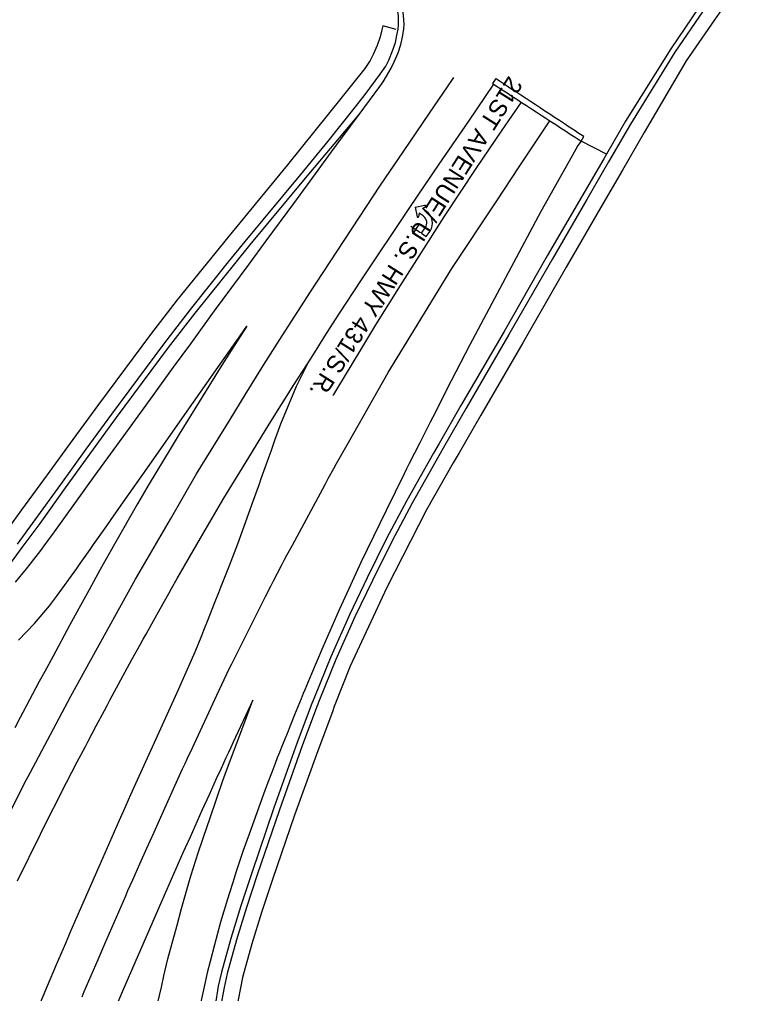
# Model space of a CAD drawing. Extents: x 1729281 to 1732101, y 650763 to 653805.
# Drawn here: x 1730490.5 to 1730745, y 652950.8 to 653286.3 of the extents above; entities that cross this region are included whole.
import ezdxf

# ---------------------------------------------------------------- set-up
doc = ezdxf.new("R2010")
doc.units = 0
for name, color, linetype in [('SURVEY - ROADSIDE BARRIERS with Text', 7, 'Continuous'), ('SURVEY - TRAFFIC CONTROL - Pavement Marking - Points - Locators', 7, 'Continuous'), ('SURVEY - TRAFFIC CONTROL - Pavement Marking with Text', 7, 'Continuous'), ('SURVEY - TRANSPORTATION - Features', 7, 'Continuous'), ('SURVEY - TRANSPORTATION - Roads', 7, 'Continuous'), ('SURVEY - TRANSPORTATION - Roads Text', 7, 'Continuous')]:
    doc.layers.add(name, color=color, linetype=linetype)

msp = doc.modelspace()

# ---------------------------------------------------------------- linework, layer by layer
at = {"layer": 'SURVEY - ROADSIDE BARRIERS with Text'}
for points in [[(1730614.71, 653267.4), (1730616.59, 653270.23), (1730617.64, 653272.3), (1730618.98, 653275.43), (1730619.91, 653278.38), (1730620.45, 653280.88), (1730620.86, 653282.91), (1730620.96, 653284.51), (1730620.97, 653287.52), (1730620.53, 653290.44), (1730619.7, 653293.26), (1730617.79, 653297.02), (1730615.82, 653299.96), (1730613.2, 653303.08), (1730610.03, 653306.4), (1730606.9, 653309.12), (1730602.9, 653312.06), (1730599.11, 653314.37), (1730596.37, 653315.86), (1730591.15, 653318.2), (1730327.77, 653357.56)], [(1730725.93, 653289.21), (1730716.21, 653275.07), (1730700.85, 653250.26), (1730693.33, 653237.27), (1730685.86, 653224.26), (1730673.98, 653203.8), (1730658.98, 653177.81), (1730644.3, 653152.43), (1730636.8, 653139.41), (1730634.86, 653136.02), (1730625.71, 653119.71), (1730618.7, 653106.52), (1730611.99, 653093.08), (1730605.99, 653080.51), (1730599.46, 653065.89), (1730593.81, 653052)]]:
    msp.add_lwpolyline(points, dxfattribs=at)
at = {"layer": 'SURVEY - TRAFFIC CONTROL - Pavement Marking - Points - Locators'}
for p, q in [((1730625.24, 653215.15), (1730628.55, 653212.89)), ((1730628.03, 653215.67), (1730625.76, 653212.37))]:
    msp.add_line(p, q, dxfattribs=at)
at = {"layer": 'SURVEY - TRAFFIC CONTROL - Pavement Marking with Text'}
for p, q in [((1730626.76, 653221.67), (1730630.08, 653222.29)), ((1730626.76, 653221.67), (1730627.38, 653218.35)), ((1730628.12, 653219.55), (1730627.87, 653218.34)), ((1730629.45, 653218.63), (1730628.12, 653219.55)), ((1730629.23, 653221.17), (1730630.26, 653221.84)), ((1730630.57, 653220.26), (1730629.23, 653221.17)), ((1730628.92, 653212.63), (1730630.22, 653214.53)), ((1730630.55, 653211.52), (1730631.85, 653213.42)), ((1730628.92, 653212.63), (1730630.55, 653211.52))]:
    msp.add_line(p, q, dxfattribs=at)
for points in [[(1730481.48, 653001.85), (1730492.24, 653023.27), (1730494.09, 653026.81), (1730508.17, 653053.26), (1730514.89, 653065.53), (1730530.41, 653093.47), (1730534.41, 653100.39), (1730542.44, 653114.2), (1730551.48, 653129.75), (1730562.97, 653148.49), (1730568.18, 653157.02), (1730574.53, 653167.19), (1730580.98, 653177.31), (1730590.64, 653192.49), (1730595.02, 653199.18), (1730604.89, 653214.23), (1730614.81, 653229.24), (1730622.67, 653240.83), (1730631.66, 653254.07), (1730639.53, 653265.65), (1730639.99, 653266.33)], [(1730489.73, 652989.58), (1730497.65, 653005.72), (1730499.45, 653009.29), (1730502.14, 653014.64), (1730506.71, 653023.52), (1730508.54, 653027.07), (1730510.38, 653030.62), (1730513.18, 653035.92), (1730514.11, 653037.68), (1730516.91, 653042.98), (1730519.72, 653048.27), (1730520.67, 653050.03), (1730521.62, 653051.79), (1730529.21, 653065.85), (1730532.12, 653071.09), (1730533.09, 653072.84), (1730534.05, 653074.58), (1730535.99, 653078.08), (1730538.91, 653083.31), (1730541.86, 653088.53), (1730542.85, 653090.26), (1730544.81, 653093.74), (1730552.78, 653107.59), (1730560.88, 653121.37), (1730568.13, 653133.33), (1730576.5, 653146.95), (1730584.99, 653160.5), (1730590.91, 653169.69), (1730596.23, 653178.15), (1730600.57, 653184.86), (1730608.22, 653196.58), (1730624.94, 653221.49), (1730635, 653236.41), (1730645.2, 653251.25), (1730653.82, 653263.99)], [(1730683.88, 653244.39), (1730684.78, 653245.95), (1730683.11, 653247.05), (1730681.44, 653248.15), (1730679.77, 653249.25), (1730678.1, 653250.35), (1730676.43, 653251.45), (1730674.76, 653252.55), (1730673.09, 653253.65), (1730671.42, 653254.75), (1730669.75, 653255.85), (1730668.08, 653256.95), (1730666.41, 653258.05), (1730664.74, 653259.15), (1730663.07, 653260.25), (1730661.4, 653261.35), (1730659.73, 653262.45), (1730658.06, 653263.55), (1730656.4, 653264.65), (1730654.73, 653265.75), (1730654.48, 653265.91), (1730653.34, 653264.28)], [(1730653.34, 653264.28), (1730655.02, 653263.18), (1730656.7, 653262.09), (1730658.37, 653261), (1730660.05, 653259.91), (1730661.72, 653258.82), (1730663.4, 653257.73), (1730665.08, 653256.64), (1730666.75, 653255.55), (1730668.43, 653254.46), (1730670.1, 653253.36), (1730671.78, 653252.27), (1730673.45, 653251.18), (1730675.13, 653250.09), (1730676.81, 653249), (1730678.48, 653247.91), (1730680.16, 653246.82), (1730681.83, 653245.73), (1730683.51, 653244.64), (1730683.88, 653244.39)], [(1730663.28, 653257.8), (1730656.61, 653248.2), (1730647.61, 653234.97), (1730636.6, 653218.27), (1730627.95, 653204.81), (1730621.54, 653194.67), (1730613.08, 653181.1), (1730607.92, 653172.54), (1730599.69, 653158.83), (1730598.66, 653157.12), (1730598.35, 653156.61)], [(1730512, 652949.62), (1730512.77, 652951.47), (1730514.34, 652955.14), (1730515.93, 652958.8), (1730517.52, 652962.47), (1730519.9, 652967.97), (1730520.69, 652969.8), (1730521.49, 652971.63), (1730523.07, 652975.3), (1730526.25, 652982.63), (1730527.04, 652984.46), (1730527.83, 652986.29), (1730529.45, 652989.95), (1730531.08, 652993.59), (1730531.9, 652995.42), (1730534.34, 653000.89), (1730536.79, 653006.36), (1730540.05, 653013.65), (1730544.94, 653024.59), (1730546.63, 653028.21), (1730547.47, 653030.02), (1730548.32, 653031.83), (1730550, 653035.45), (1730558.43, 653053.55), (1730562.7, 653062.58), (1730563.59, 653064.36), (1730564.49, 653066.15), (1730575.23, 653087.57), (1730577.02, 653091.14), (1730577.91, 653092.92), (1730580.66, 653098.25), (1730581.6, 653100.01), (1730582.55, 653101.76), (1730584.45, 653105.28), (1730594.88, 653124.62), (1730595.82, 653126.38), (1730596.77, 653128.13), (1730598.68, 653131.64), (1730599.67, 653133.38), (1730605.59, 653143.81), (1730610.52, 653152.49), (1730617.43, 653164.66), (1730620.54, 653169.79), (1730629.95, 653185.12), (1730639.37, 653200.46), (1730654.8, 653223.82), (1730662.51, 653235.5), (1730668.07, 653243.81), (1730673.15, 653251.38)], [(1730494.71, 652940.56), (1730500.09, 652953.46), (1730503.24, 652960.81), (1730505.59, 652966.32), (1730506.38, 652968.16), (1730507.95, 652971.83), (1730508.73, 652973.66), (1730510.3, 652977.33), (1730519.11, 652997.46), (1730524.76, 653010.25), (1730526.4, 653013.89), (1730528.84, 653019.36), (1730536.23, 653035.75), (1730545.32, 653055.74), (1730546.98, 653059.37), (1730550.95, 653068.53), (1730553.22, 653074.08), (1730553.96, 653075.93), (1730555.45, 653079.64), (1730557.67, 653085.2), (1730559.13, 653088.92), (1730559.86, 653090.78), (1730562.79, 653098.21), (1730565.62, 653105.68), (1730571.07, 653120.7), (1730573.07, 653126.34), (1730573.74, 653128.22), (1730575.07, 653131.99), (1730576.41, 653135.76), (1730577.08, 653137.64), (1730578.42, 653141.4), (1730580.47, 653147.03), (1730585.81, 653159.96), (1730589.86, 653167.99)]]:
    msp.add_lwpolyline(points, dxfattribs=at)
for centre, radius, start, end in [((1730630.13, 653222.05), 0.246, 303.1463, 100.5946), ((1730627.79, 653216.2), 4.92, 325.5946, 55.5946), ((1730627.63, 653218.39), 0.246, 190.5946, 348.0878), ((1730627.79, 653216.2), 2.95, 325.5946, 55.5946)]:
    msp.add_arc(centre, radius, start, end, dxfattribs=at)
at = {"layer": 'SURVEY - TRANSPORTATION - Features'}
for points in [[(1730737.97, 653298.15), (1730737.38, 653297.24), (1730734.67, 653293.21), (1730729.82, 653286.16), (1730720.1, 653272.02), (1730705.64, 653247.38), (1730698.15, 653234.38), (1730690.58, 653221.43), (1730678.7, 653200.97), (1730663.77, 653174.94), (1730649.34, 653150.02), (1730641.83, 653136.99), (1730639.85, 653133.62), (1730630.65, 653117.34), (1730616.96, 653090.7), (1730604.4, 653063.52), (1730598.78, 653049.61)], [(1730620.24, 653282.85), (1730615.59, 653284.06), (1730615.26, 653282.74), (1730614.65, 653280.27), (1730613.67, 653277.34), (1730612.31, 653274.22), (1730611.25, 653272.16), (1730609.43, 653269.39)], [(1730609.43, 653269.39), (1730601.62, 653259.61), (1730582.78, 653236.22), (1730563.72, 653213.03), (1730544.77, 653189.68), (1730535.59, 653177.78), (1730526.59, 653165.78), (1730517.68, 653153.72), (1730508.84, 653141.61), (1730500.05, 653129.49), (1730491.2, 653117.35), (1730485.19, 653109.17), (1730479.55, 653101.28), (1730473.84, 653094.03), (1730471.07, 653090.99), (1730469.52, 653089.49), (1730468.39, 653087.93), (1730465.09, 653085.08), (1730463.42, 653083.93), (1730458.79, 653080.79), (1730451.04, 653076.23), (1730447.64, 653074.44), (1730449.28, 653071.25), (1730449.99, 653070.09)], [(1730489.82, 653105.61), (1730495.87, 653113.98), (1730504.68, 653126.12), (1730513.47, 653138.25), (1730522.27, 653150.39), (1730531.18, 653162.45), (1730540.19, 653174.43), (1730549.32, 653186.35), (1730562.45, 653202.84), (1730568.13, 653209.78), (1730587.35, 653232.87), (1730596.8, 653244.36), (1730606.21, 653256.24), (1730609.51, 653260.39), (1730614.71, 653267.4)], [(1730450.28, 653069.61), (1730451.48, 653067.67), (1730455.12, 653069.61), (1730463.19, 653074.69), (1730468.27, 653078.11), (1730470.28, 653079.67), (1730473.67, 653082.43), (1730475.07, 653083.7), (1730476.9, 653085.7), (1730479.63, 653088.77), (1730485.55, 653096.44), (1730491.43, 653104.37), (1730497.58, 653112.74), (1730506.29, 653124.96), (1730515.08, 653137.08), (1730523.91, 653149.2), (1730532.8, 653161.27), (1730541.82, 653173.25), (1730550.93, 653185.18), (1730569.79, 653208.56), (1730589, 653231.66), (1730607.41, 653253.55)], [(1730692.6, 653239.86), (1730691.68, 653238.27), (1730684.07, 653225.34), (1730672.24, 653204.84), (1730657.33, 653178.8), (1730642.49, 653153.3), (1730635.02, 653140.26), (1730633.02, 653136.9), (1730623.9, 653120.58), (1730616.91, 653107.48), (1730610.21, 653093.94), (1730604.2, 653081.41), (1730597.65, 653066.76), (1730592.04, 653052.85)], [(1730593.81, 653052), (1730593.01, 653049.91), (1730587.95, 653036.51), (1730579.97, 653014.12), (1730572.35, 652991.72), (1730568.61, 652980.38), (1730565.18, 652969.25), (1730561.99, 652957.71), (1730560.9, 652952.93), (1730559.72, 652946.25), (1730558.22, 652934.65), (1730557.04, 652922.7), (1730556.4, 652914.49), (1730556.03, 652908.94), (1730555.51, 652901.33), (1730555.1, 652891.72), (1730554.9, 652887.89), (1730554.66, 652884.77)], [(1730592.04, 653052.85), (1730591.18, 653050.64), (1730586.09, 653037.26), (1730578.08, 653014.81), (1730570.43, 652992.33), (1730566.69, 652980.98), (1730563.23, 652969.76), (1730560.07, 652958.21), (1730558.94, 652953.33), (1730557.81, 652946.66)], [(1730598.78, 653049.61), (1730598.21, 653047.82), (1730593.16, 653034.42), (1730585.23, 653012.19), (1730577.61, 652990.04), (1730573.85, 652978.74), (1730570.46, 652967.88), (1730567.29, 652956.32), (1730565.12, 652945.09), (1730563.69, 652933.72), (1730562.37, 652921.79), (1730561.79, 652913.85), (1730561.35, 652908.33), (1730560.88, 652900.71), (1730560.67, 652891.49), (1730560.52, 652887.66), (1730560.44, 652885.09), (1730555.27, 652884.74)]]:
    msp.add_lwpolyline(points, dxfattribs=at)
at = {"layer": 'SURVEY - TRANSPORTATION - Roads'}
for points in [[(1731080.5, 653780.05), (1730777.76, 653370.42), (1730768.67, 653356.68), (1730762.82, 653347.7), (1730759.6, 653342.8), (1730758.15, 653340.72), (1730757.59, 653339.86), (1730749.27, 653327.53), (1730740.9, 653315.08), (1730732.5, 653302.44), (1730731.87, 653301.56), (1730729.19, 653297.5), (1730724.4, 653290.41), (1730714.81, 653276.16), (1730699.21, 653251.24), (1730692.6, 653239.86)], [(1730616.87, 653266.71), (1730618.46, 653269.56), (1730619.5, 653271.64), (1730620.85, 653274.76), (1730621.78, 653277.7), (1730622.32, 653280.2), (1730622.84, 653283.07), (1730622.93, 653284.68), (1730622.7, 653287.67), (1730622.42, 653290.6), (1730621.29, 653294.51), (1730619.4, 653298.27), (1730617.42, 653301.21), (1730614.79, 653304.32), (1730611.29, 653307.98), (1730608.15, 653310.7), (1730604.15, 653313.63), (1730599.99, 653316.18), (1730597.25, 653317.67), (1730592.03, 653320.02), (1730327.8, 653362.26)], [(1730489.14, 653092.44), (1730492.9, 653097.1), (1730494.12, 653098.67), (1730497.78, 653103.42), (1730499, 653105), (1730502.51, 653109.86), (1730509.49, 653119.6), (1730516.54, 653129.3), (1730527.1, 653143.85), (1730536.5, 653156.79), (1730538.85, 653160.02), (1730543.55, 653166.49), (1730549.43, 653174.57), (1730552.95, 653179.42), (1730557.67, 653185.88), (1730563.6, 653193.93), (1730569.53, 653201.98), (1730575.46, 653210.03), (1730584.94, 653222.92), (1730589.67, 653229.36), (1730597.95, 653240.65), (1730601.5, 653245.48), (1730607.41, 653253.55), (1730614.51, 653263.22), (1730615.71, 653264.82), (1730616.87, 653266.71)], [(1730692.6, 653239.86), (1730683.88, 653244.39), (1730682.74, 653242.83), (1730680.77, 653239.34), (1730670.06, 653220.12), (1730660.59, 653202.51), (1730654.94, 653191.92), (1730650.25, 653183.09), (1730645.61, 653174.24), (1730639.17, 653161.81), (1730632.82, 653149.35), (1730631.91, 653147.57), (1730628.28, 653140.45), (1730624.67, 653133.32), (1730623.78, 653131.53), (1730622.89, 653129.74), (1730616.69, 653117.22), (1730608.05, 653099.23), (1730603.89, 653090.16), (1730600.58, 653082.9), (1730594.95, 653070.11), (1730591.02, 653060.94), (1730588.7, 653055.42), (1730588.17, 653054.17)], [(1730490.08, 653072.46), (1730495.61, 653078.24), (1730500.8, 653084.31), (1730503.22, 653087.49), (1730510.2, 653097.22), (1730511.35, 653098.86), (1730512.5, 653100.49), (1730514.8, 653103.76), (1730515.95, 653105.4), (1730520.54, 653111.93), (1730522.84, 653115.2), (1730526.29, 653120.1), (1730534.34, 653131.54), (1730545.84, 653147.88), (1730559.53, 653167.58), (1730566.46, 653177.37), (1730568.81, 653180.7), (1730563.4, 653172.29), (1730560.15, 653167.25), (1730545.45, 653143.44), (1730542.33, 653138.32), (1730535.14, 653126.31), (1730531.09, 653119.43), (1730523.17, 653105.54), (1730518.3, 653096.82), (1730514.41, 653089.84), (1730509.64, 653081.06), (1730507.74, 653077.55), (1730502.02, 653067.01), (1730499.16, 653061.74), (1730497.26, 653058.23), (1730491.66, 653047.63), (1730490.75, 653045.86), (1730488.91, 653042.31)], [(1730570.82, 653051.88), (1730564.09, 653037.4), (1730563.25, 653035.59), (1730562.41, 653033.78), (1730561.57, 653031.96), (1730559.91, 653028.33), (1730558.25, 653024.7), (1730557.42, 653022.88), (1730555.75, 653019.25), (1730553.27, 653013.8), (1730552.45, 653011.97), (1730551.64, 653010.15), (1730549.2, 653004.68), (1730547.57, 653001.03), (1730546.76, 652999.21), (1730545.95, 652997.38), (1730542.72, 652990.08), (1730540.3, 652984.6), (1730539.49, 652982.77), (1730525.99, 652951.61), (1730513.59, 652922.15)], [(1730532.91, 652916.65), (1730533.77, 652923.61), (1730535.06, 652931.49), (1730536.11, 652937.4), (1730537.62, 652945.24), (1730538, 652947.2), (1730539.33, 652953.04), (1730540.23, 652956.93), (1730540.69, 652958.88), (1730541.59, 652962.77), (1730544.72, 652974.34), (1730546.31, 652980.11), (1730549.03, 652989.72), (1730549.57, 652991.64), (1730552.02, 652999.24), (1730555.21, 653008.7), (1730555.86, 653010.59), (1730558.46, 653018.14), (1730560.42, 653023.8), (1730561.73, 653027.58), (1730567.38, 653042.51), (1730570.82, 653051.88)], [(1730588.17, 653054.17), (1730587.43, 653052.31), (1730585.19, 653046.75), (1730583.7, 653043.05), (1730582.96, 653041.2), (1730580.72, 653035.64), (1730579.98, 653033.79), (1730579.23, 653031.93), (1730578.49, 653030.08), (1730577.77, 653028.22), (1730575.7, 653022.59), (1730575.01, 653020.72), (1730569.51, 653005.72), (1730567.44, 653000.09), (1730565.01, 652992.48), (1730564.42, 652990.58), (1730563.82, 652988.67), (1730562.03, 652982.96), (1730561.43, 652981.05), (1730560.83, 652979.14), (1730559.66, 652975.33), (1730558.65, 652971.46), (1730557.64, 652967.6), (1730556.13, 652961.81), (1730555.12, 652957.94), (1730553.8, 652952.1), (1730552.12, 652944.29)]]:
    msp.add_lwpolyline(points, dxfattribs=at)

# ---------------------------------------------------------------- texts
at = {"layer": 'SURVEY - TRANSPORTATION - Roads Text'}
msp.add_text('21ST AVENUE/ U.S. HWY 431/S.R.', height=6, rotation=237.6322, dxfattribs=at).set_placement((1730659.02, 653267.17))

doc.saveas('drawing.dxf')
